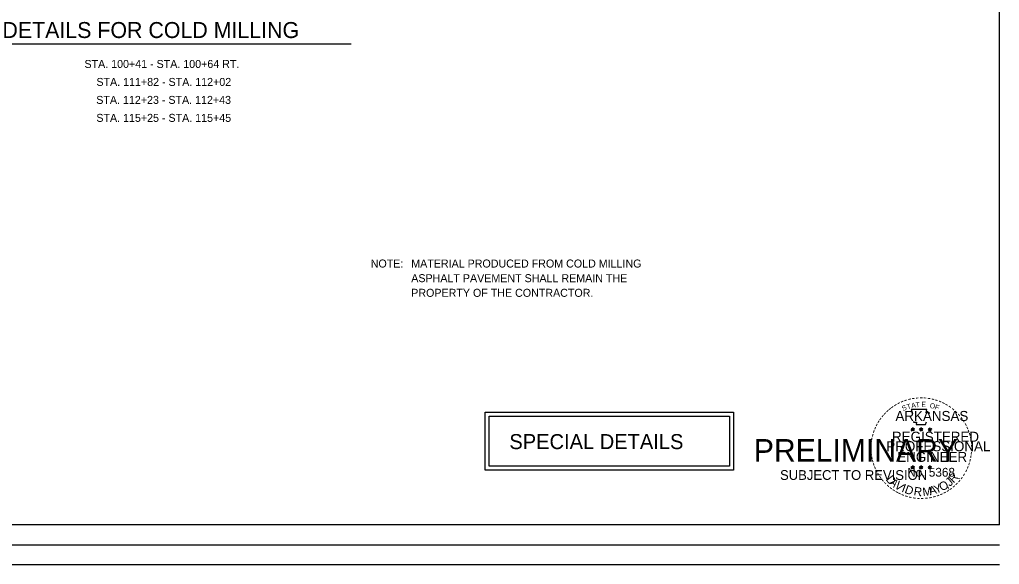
# Model space of a CAD drawing. Extents: x 1944905 to 1956777, y 763871 to 764977.
# Drawn here: x 1952380 to 1953359, y 763871 to 764415 of the extents above; entities that cross this region are included whole.
import ezdxf

# ---------------------------------------------------------------- set-up
doc = ezdxf.new("R2010")
doc.units = 0
for name, color, linetype in [('Default', 7, 'Continuous'), ('R_Border PE', 7, 'Continuous'), ('R_Dimension', 7, 'Continuous')]:
    doc.layers.add(name, color=color, linetype=linetype)

msp = doc.modelspace()

# ---------------------------------------------------------------- linework, layer by layer
at = {"layer": 'Default'}
for p, q in [((1953358.8, 763910.07), (1953358.8, 764937.29)), ((1953358.8, 763910.07), (1951777.89, 763910.07)), ((1951745.05, 763890.36), (1953358.8, 763890.36)), ((1951745.05, 763870.67), (1953358.8, 763870.67))]:
    msp.add_line(p, q, dxfattribs=at)
for points in [[(1952844.89, 764022.9), (1953092.9, 764022.9), (1953092.9, 763964.87), (1952844.89, 763964.87)], [(1952848.89, 764018.9), (1953088.9, 764018.9), (1953088.9, 763968.87), (1952848.89, 763968.87)]]:
    msp.add_lwpolyline(points, close=True, dxfattribs=at)
at = {"layer": 'R_Border PE'}
for p, q in [((1953270.46, 764006.04), (1953272.16, 764005.49)), ((1953270.46, 764006.04), (1953271.71, 764005.89)), ((1953270.46, 764006.04), (1953271.71, 764005.84)), ((1953270.46, 764006.04), (1953271.66, 764005.74)), ((1953270.46, 764006.04), (1953271.66, 764005.54)), ((1953270.46, 764006.04), (1953271.61, 764005.44)), ((1953270.46, 764006.04), (1953271.61, 764005.34)), ((1953272.16, 764007.29), (1953271.91, 764006.09)), ((1953272.16, 764007.29), (1953271.96, 764006.04)), ((1953272.16, 764007.29), (1953272.11, 764006.04)), ((1953272.16, 764005.49), (1953272.16, 764007.29)), ((1953272.16, 764007.29), (1953272.51, 764006.04)), ((1953272.16, 764007.29), (1953272.41, 764006.04)), ((1953272.16, 764007.29), (1953272.31, 764006.09)), ((1953273.91, 764006.04), (1953272.16, 764005.49)), ((1953273.91, 764006.04), (1953272.41, 764005.94)), ((1953273.91, 764006.04), (1953272.51, 764005.79)), ((1953273.91, 764006.04), (1953272.51, 764005.69)), ((1953273.91, 764006.04), (1953272.81, 764005.59)), ((1953273.91, 764006.04), (1953272.91, 764005.54)), ((1953273.91, 764006.04), (1953272.96, 764005.49)), ((1953278.76, 764006.04), (1953280.51, 764005.49)), ((1953278.76, 764006.04), (1953280.06, 764005.89)), ((1953278.76, 764006.04), (1953280.06, 764005.84)), ((1953278.76, 764006.04), (1953280.01, 764005.74)), ((1953278.76, 764006.04), (1953280.01, 764005.54)), ((1953278.76, 764006.04), (1953279.96, 764005.44)), ((1953278.76, 764006.04), (1953279.96, 764005.34)), ((1953280.51, 764007.29), (1953280.26, 764006.09)), ((1953280.51, 764007.29), (1953280.31, 764006.04)), ((1953280.51, 764007.29), (1953280.46, 764006.04)), ((1953280.51, 764005.49), (1953280.51, 764007.29)), ((1953280.51, 764007.29), (1953280.86, 764006.04)), ((1953280.51, 764007.29), (1953280.76, 764006.04)), ((1953280.51, 764007.29), (1953280.66, 764006.09)), ((1953282.26, 764006.04), (1953280.51, 764005.49)), ((1953282.26, 764006.04), (1953280.71, 764005.94)), ((1953282.26, 764006.04), (1953280.81, 764005.79)), ((1953282.26, 764006.04), (1953280.81, 764005.69)), ((1953282.26, 764006.04), (1953281.16, 764005.59)), ((1953282.26, 764006.04), (1953281.26, 764005.54)), ((1953282.26, 764006.04), (1953281.31, 764005.49)), ((1953287.61, 764005.99), (1953289.36, 764005.44)), ((1953287.61, 764005.99), (1953288.91, 764005.84)), ((1953287.61, 764005.99), (1953288.91, 764005.74)), ((1953287.61, 764005.99), (1953288.86, 764005.64)), ((1953287.61, 764005.99), (1953288.81, 764005.49)), ((1953287.61, 764005.99), (1953288.81, 764005.39)), ((1953287.61, 764005.99), (1953288.81, 764005.29)), ((1953289.36, 764007.24), (1953289.06, 764006.04)), ((1953289.36, 764007.24), (1953289.16, 764005.99)), ((1953289.36, 764007.24), (1953289.26, 764005.99)), ((1953289.36, 764005.44), (1953289.36, 764007.24)), ((1953289.36, 764007.24), (1953289.71, 764005.99)), ((1953289.36, 764007.24), (1953289.61, 764005.99)), ((1953289.36, 764007.24), (1953289.46, 764006.04)), ((1953291.11, 764005.99), (1953289.36, 764005.44)), ((1953291.11, 764005.99), (1953289.56, 764005.89)), ((1953291.11, 764005.99), (1953289.66, 764005.74)), ((1953291.11, 764005.99), (1953289.66, 764005.64)), ((1953291.11, 764005.99), (1953290.01, 764005.54)), ((1953291.11, 764005.99), (1953290.06, 764005.49)), ((1953291.11, 764005.99), (1953290.16, 764005.44)), ((1953271.11, 764003.99), (1953272.16, 764005.49)), ((1953271.11, 764003.99), (1953271.66, 764005.39)), ((1953271.11, 764003.99), (1953271.71, 764005.24)), ((1953271.11, 764003.99), (1953271.81, 764005.19)), ((1953271.11, 764003.99), (1953272.16, 764005.09)), ((1953271.11, 764003.99), (1953271.96, 764005.04)), ((1953271.11, 764003.99), (1953272.21, 764004.94)), ((1953273.26, 764003.99), (1953272.16, 764005.49)), ((1953273.26, 764003.99), (1953272.16, 764005.09)), ((1953273.26, 764003.99), (1953272.16, 764004.94)), ((1953273.26, 764003.99), (1953272.36, 764005.04)), ((1953273.26, 764003.99), (1953272.51, 764005.24)), ((1953273.26, 764003.99), (1953272.56, 764005.44)), ((1953273.26, 764003.99), (1953272.66, 764005.44)), ((1953279.46, 764003.99), (1953280.51, 764005.49)), ((1953279.46, 764003.99), (1953280.01, 764005.39)), ((1953279.46, 764003.99), (1953280.06, 764005.24)), ((1953279.46, 764003.99), (1953280.16, 764005.19)), ((1953279.46, 764003.99), (1953280.51, 764005.09)), ((1953279.46, 764003.99), (1953280.31, 764005.04)), ((1953279.46, 764003.99), (1953280.56, 764004.94)), ((1953281.61, 764003.99), (1953280.51, 764005.49)), ((1953281.61, 764003.99), (1953280.51, 764005.09)), ((1953281.61, 764003.99), (1953280.51, 764004.94)), ((1953281.61, 764003.99), (1953280.71, 764005.04)), ((1953281.61, 764003.99), (1953280.86, 764005.24)), ((1953281.61, 764003.99), (1953280.91, 764005.44)), ((1953281.61, 764003.99), (1953281.01, 764005.44)), ((1953288.31, 764003.94), (1953289.36, 764005.44)), ((1953288.31, 764003.94), (1953288.86, 764005.34)), ((1953288.31, 764003.94), (1953288.91, 764005.14)), ((1953288.31, 764003.94), (1953289.01, 764005.14)), ((1953288.31, 764003.94), (1953289.36, 764005.04)), ((1953288.31, 764003.94), (1953289.16, 764004.99)), ((1953288.31, 764003.94), (1953289.41, 764004.89)), ((1953290.41, 764003.94), (1953289.36, 764005.44)), ((1953290.41, 764003.94), (1953289.36, 764005.04)), ((1953290.41, 764003.94), (1953289.36, 764004.89)), ((1953290.41, 764003.94), (1953289.56, 764004.99)), ((1953290.41, 764003.94), (1953289.71, 764005.19)), ((1953290.41, 764003.94), (1953289.76, 764005.39)), ((1953290.41, 764003.94), (1953289.86, 764005.39)), ((1953270.41, 763968.19), (1953272.16, 763967.64)), ((1953270.41, 763968.19), (1953271.71, 763968.04)), ((1953270.41, 763968.19), (1953271.71, 763967.94)), ((1953270.41, 763968.19), (1953271.66, 763967.84)), ((1953270.41, 763968.19), (1953271.61, 763967.69)), ((1953270.41, 763968.19), (1953271.61, 763967.59)), ((1953270.41, 763968.19), (1953271.61, 763967.44)), ((1953271.11, 763966.14), (1953272.16, 763967.64)), ((1953271.11, 763966.14), (1953271.66, 763967.54)), ((1953271.11, 763966.14), (1953271.71, 763967.34)), ((1953271.11, 763966.14), (1953271.81, 763967.29)), ((1953271.11, 763966.14), (1953272.16, 763967.24)), ((1953271.11, 763966.14), (1953271.96, 763967.19)), ((1953271.11, 763966.14), (1953272.21, 763967.09)), ((1953272.16, 763969.44), (1953271.86, 763968.24)), ((1953272.16, 763969.44), (1953271.96, 763968.19)), ((1953272.16, 763969.44), (1953272.06, 763968.19)), ((1953272.16, 763967.64), (1953272.16, 763969.44)), ((1953272.16, 763969.44), (1953272.51, 763968.19)), ((1953272.16, 763969.44), (1953272.41, 763968.19)), ((1953272.16, 763969.44), (1953272.26, 763968.19)), ((1953273.91, 763968.19), (1953272.16, 763967.64)), ((1953273.21, 763966.14), (1953272.16, 763967.64)), ((1953273.21, 763966.14), (1953272.16, 763967.19)), ((1953273.21, 763966.14), (1953272.16, 763967.09)), ((1953273.91, 763968.19), (1953272.36, 763968.09)), ((1953273.21, 763966.14), (1953272.36, 763967.19)), ((1953273.91, 763968.19), (1953272.46, 763967.94)), ((1953273.91, 763968.19), (1953272.46, 763967.84)), ((1953273.21, 763966.14), (1953272.51, 763967.34)), ((1953273.21, 763966.14), (1953272.56, 763967.59)), ((1953273.21, 763966.14), (1953272.66, 763967.59)), ((1953273.91, 763968.19), (1953272.81, 763967.74)), ((1953273.91, 763968.19), (1953272.86, 763967.69)), ((1953273.91, 763968.19), (1953272.96, 763967.59)), ((1953278.76, 763968.19), (1953280.51, 763967.64)), ((1953278.76, 763968.19), (1953280.06, 763968.04)), ((1953278.76, 763968.19), (1953280.01, 763967.94)), ((1953278.76, 763968.19), (1953280.01, 763967.84)), ((1953278.76, 763968.19), (1953279.96, 763967.69)), ((1953278.76, 763968.19), (1953279.96, 763967.59)), ((1953278.76, 763968.19), (1953279.96, 763967.44)), ((1953279.41, 763966.14), (1953280.51, 763967.64)), ((1953279.41, 763966.14), (1953280.01, 763967.54)), ((1953279.41, 763966.14), (1953280.06, 763967.34)), ((1953279.41, 763966.14), (1953280.16, 763967.29)), ((1953279.41, 763966.14), (1953280.51, 763967.24)), ((1953279.41, 763966.14), (1953280.31, 763967.19)), ((1953279.41, 763966.14), (1953280.51, 763967.09)), ((1953280.51, 763969.44), (1953280.21, 763968.24)), ((1953280.51, 763969.44), (1953280.31, 763968.19)), ((1953280.51, 763969.44), (1953280.41, 763968.19)), ((1953280.51, 763967.64), (1953280.51, 763969.44)), ((1953280.51, 763969.44), (1953280.86, 763968.19)), ((1953280.51, 763969.44), (1953280.76, 763968.19)), ((1953280.51, 763969.44), (1953280.61, 763968.19)), ((1953282.26, 763968.19), (1953280.51, 763967.64)), ((1953281.56, 763966.14), (1953280.51, 763967.64)), ((1953281.56, 763966.14), (1953280.51, 763967.19)), ((1953281.56, 763966.14), (1953280.51, 763967.09)), ((1953282.26, 763968.19), (1953280.71, 763968.09)), ((1953281.56, 763966.14), (1953280.71, 763967.19)), ((1953282.26, 763968.19), (1953280.81, 763967.94)), ((1953282.26, 763968.19), (1953280.81, 763967.84)), ((1953281.56, 763966.14), (1953280.86, 763967.34)), ((1953281.56, 763966.14), (1953280.91, 763967.59)), ((1953281.56, 763966.14), (1953281.01, 763967.59)), ((1953282.26, 763968.19), (1953281.11, 763967.74)), ((1953282.26, 763968.19), (1953281.21, 763967.69)), ((1953282.26, 763968.19), (1953281.31, 763967.59)), ((1953287.61, 763968.14), (1953289.36, 763967.54)), ((1953287.61, 763968.14), (1953288.86, 763967.99)), ((1953287.61, 763968.14), (1953288.86, 763967.89)), ((1953287.61, 763968.14), (1953288.81, 763967.79)), ((1953287.61, 763968.14), (1953288.81, 763967.64)), ((1953287.61, 763968.14), (1953288.76, 763967.49)), ((1953287.61, 763968.14), (1953288.76, 763967.39)), ((1953288.26, 763966.09), (1953289.36, 763967.54)), ((1953288.26, 763966.09), (1953288.81, 763967.44)), ((1953288.26, 763966.09), (1953288.91, 763967.29)), ((1953288.26, 763966.09), (1953289.01, 763967.24)), ((1953288.26, 763966.09), (1953289.16, 763967.14)), ((1953288.26, 763966.09), (1953289.31, 763967.14)), ((1953288.26, 763966.09), (1953289.36, 763967.04)), ((1953289.36, 763969.39), (1953289.06, 763968.14)), ((1953289.36, 763969.39), (1953289.16, 763968.14)), ((1953289.36, 763969.39), (1953289.26, 763968.14)), ((1953290.41, 763966.09), (1953289.31, 763967.14)), ((1953290.41, 763966.09), (1953289.31, 763966.99)), ((1953289.36, 763967.54), (1953289.36, 763969.39)), ((1953289.36, 763969.39), (1953289.66, 763968.14)), ((1953289.36, 763969.39), (1953289.61, 763968.14)), ((1953289.36, 763969.39), (1953289.46, 763968.14)), ((1953291.06, 763968.14), (1953289.36, 763967.54)), ((1953290.41, 763966.09), (1953289.36, 763967.54)), ((1953290.41, 763966.09), (1953289.51, 763967.14)), ((1953291.06, 763968.14), (1953289.56, 763967.99)), ((1953291.06, 763968.14), (1953289.66, 763967.89)), ((1953291.06, 763968.14), (1953289.66, 763967.79)), ((1953290.41, 763966.09), (1953289.71, 763967.54)), ((1953290.41, 763966.09), (1953289.71, 763967.29)), ((1953290.41, 763966.09), (1953289.86, 763967.54)), ((1953291.06, 763968.14), (1953289.96, 763967.64)), ((1953291.06, 763968.14), (1953290.06, 763967.59)), ((1953291.06, 763968.14), (1953290.11, 763967.54))]:
    msp.add_line(p, q, dxfattribs=at)
for points in [[(1953270.66, 764025.44), (1953272.01, 764021.29)], [(1953288.21, 764020.84), (1953288.91, 764022.24), (1953285.46, 764022.14), (1953286.21, 764025.44), (1953270.66, 764025.44)], [(1953272.16, 764007.29), (1953273.26, 764003.99), (1953270.46, 764006.04), (1953273.91, 764006.04), (1953271.11, 764003.99), (1953272.16, 764007.29)], [(1953273.11, 764013.34), (1953273.11, 764012.89), (1953275.91, 764012.79), (1953275.66, 764010.44), (1953285.01, 764010.44), (1953286.01, 764013.09)], [(1953280.51, 764007.29), (1953281.61, 764003.99), (1953278.76, 764006.04), (1953282.26, 764006.04), (1953279.46, 764003.99), (1953280.51, 764007.29)], [(1953289.36, 764007.24), (1953290.41, 764003.94), (1953287.61, 764005.99), (1953291.11, 764005.99), (1953288.31, 764003.94), (1953289.36, 764007.24)], [(1953272.16, 763969.44), (1953273.21, 763966.14), (1953270.41, 763968.19), (1953273.91, 763968.19), (1953271.11, 763966.14), (1953272.16, 763969.44)], [(1953280.51, 763969.44), (1953281.56, 763966.14), (1953278.76, 763968.19), (1953282.26, 763968.19), (1953279.41, 763966.14), (1953280.51, 763969.44)], [(1953289.36, 763969.39), (1953290.41, 763966.09), (1953287.61, 763968.14), (1953291.06, 763968.14), (1953288.26, 763966.09), (1953289.36, 763969.39)]]:
    msp.add_lwpolyline(points, dxfattribs=at)
for centre, radius in [((1953272.16, 764005.49), 0.861), ((1953272.16, 764005.49), 0.78), ((1953272.16, 764005.49), 0.723), ((1953272.16, 764005.49), 0.664), ((1953272.16, 764005.49), 0.579), ((1953272.16, 764005.49), 0.537), ((1953272.16, 764005.49), 0.495), ((1953272.16, 764005.49), 0.426), ((1953272.16, 764005.49), 0.374), ((1953280.5, 764005.49), 0.861), ((1953280.5, 764005.49), 0.78), ((1953280.5, 764005.49), 0.723), ((1953280.5, 764005.49), 0.664), ((1953280.5, 764005.49), 0.579), ((1953280.5, 764005.49), 0.537), ((1953280.5, 764005.49), 0.495), ((1953280.5, 764005.49), 0.426), ((1953280.5, 764005.49), 0.374), ((1953289.34, 764005.43), 0.861), ((1953289.34, 764005.43), 0.78), ((1953289.34, 764005.43), 0.723), ((1953289.34, 764005.43), 0.664), ((1953289.34, 764005.43), 0.579), ((1953289.34, 764005.43), 0.537), ((1953289.34, 764005.43), 0.495), ((1953289.34, 764005.43), 0.426), ((1953272.16, 764005.49), 0.311), ((1953272.16, 764005.49), 0.248), ((1953272.16, 764005.49), 0.185), ((1953272.16, 764005.49), 0.148), ((1953272.16, 764005.49), 0.0721), ((1953280.5, 764005.49), 0.311), ((1953280.5, 764005.49), 0.248), ((1953280.5, 764005.49), 0.185), ((1953280.5, 764005.49), 0.148), ((1953280.5, 764005.49), 0.0721), ((1953289.34, 764005.43), 0.374), ((1953289.34, 764005.43), 0.311), ((1953289.34, 764005.43), 0.248), ((1953289.34, 764005.43), 0.185), ((1953289.34, 764005.43), 0.148), ((1953289.34, 764005.43), 0.0721), ((1953272.14, 763967.63), 0.861), ((1953272.14, 763967.63), 0.78), ((1953272.14, 763967.63), 0.723), ((1953272.14, 763967.63), 0.664), ((1953272.14, 763967.63), 0.579), ((1953272.14, 763967.63), 0.537), ((1953272.14, 763967.63), 0.495), ((1953272.14, 763967.63), 0.426), ((1953272.14, 763967.63), 0.374), ((1953272.14, 763967.63), 0.311), ((1953272.14, 763967.63), 0.248), ((1953272.14, 763967.63), 0.185), ((1953272.14, 763967.63), 0.148), ((1953272.14, 763967.63), 0.0721), ((1953280.48, 763967.63), 0.861), ((1953280.48, 763967.63), 0.78), ((1953280.48, 763967.63), 0.723), ((1953280.48, 763967.63), 0.664), ((1953280.48, 763967.63), 0.579), ((1953280.48, 763967.63), 0.537), ((1953280.48, 763967.63), 0.495), ((1953280.48, 763967.63), 0.426), ((1953280.48, 763967.63), 0.374), ((1953280.48, 763967.63), 0.311), ((1953280.48, 763967.63), 0.248), ((1953280.48, 763967.63), 0.185), ((1953280.48, 763967.63), 0.148), ((1953280.48, 763967.63), 0.0721), ((1953289.32, 763967.57), 0.861), ((1953289.32, 763967.57), 0.78), ((1953289.32, 763967.57), 0.723), ((1953289.32, 763967.57), 0.664), ((1953289.32, 763967.57), 0.579), ((1953289.32, 763967.57), 0.537), ((1953289.32, 763967.57), 0.495), ((1953289.32, 763967.57), 0.426), ((1953289.32, 763967.57), 0.374), ((1953289.32, 763967.57), 0.311), ((1953289.32, 763967.57), 0.248), ((1953289.32, 763967.57), 0.185), ((1953289.32, 763967.57), 0.148), ((1953289.32, 763967.57), 0.0721)]:
    msp.add_circle(centre, radius, dxfattribs=at)
at = {"layer": 'R_Dimension'}
msp.add_line((1952363.95, 764390.69), (1952710.98, 764390.69), dxfattribs=at)

# ---------------------------------------------------------------- texts
at = {"layer": 'Default'}
for s, height, p in [('SPECIAL DETAILS', 15, (1952869.08, 763985.86)), ('PRELIMINARY', 22.5, (1953113.39, 763973.37)), ('        SUBJECT TO REVISION', 9.75, (1953110.57, 763955.1))]:
    msp.add_text(s, height=height, dxfattribs=at).set_placement(p)
at = {"layer": 'R_Border PE'}
for s, height, rotation, p in [('-', 8, 19.17608, (1953264.36, 764031.09)), ('-', 8, 13.63015, (1953268.11, 764032.29)), ('-', 8, 10.21935, (1953271.51, 764033.09)), ('-', 8, 5.89682, (1953275.16, 764033.64)), ('-', 8, 0.18623, (1953279.01, 764033.99)), ('-', 8, 357.74304, (1953282.66, 764033.94)), ('-', 8, 352.16173, (1953286.36, 764033.64)), ('-', 8, 347.20489, (1953289.96, 764033.09)), ('-', 8, 342.3362, (1953293.11, 764032.29)), ('-', 8, 38.95066, (1953249.81, 764022.44)), ('-', 8, 36.23174, (1953252.16, 764024.29)), ('-', 8, 34.06357, (1953255.06, 764026.29)), ('-', 8, 28.79182, (1953258.06, 764028.14)), ('-', 8, 24.30721, (1953261.21, 764029.74)), ('S', 5, 21.59401, (1953262.41, 764023.84)), ('T', 5, 16.4036, (1953267.01, 764025.49)), ('A', 5, 11.21318, (1953271.11, 764026.74)), ('T', 5, 6.02276, (1953275.36, 764027.54)), ('E', 5, 0.83234, (1953280.91, 764028.09)), ('O', 5, 350.4515, (1953288.91, 764027.04)), ('F', 5, 340.07066, (1953293.66, 764025.94)), ('-', 8, 337.85509, (1953296.81, 764031.19)), ('-', 8, 334.12109, (1953299.96, 764029.84)), ('-', 8, 329.64089, (1953302.86, 764028.44)), ('-', 8, 325.86266, (1953306.06, 764026.59)), ('-', 8, 320.52971, (1953309.11, 764024.49)), ('-', 8, 54.23247, (1953241.31, 764012.69)), ('-', 8, 50.61417, (1953243.36, 764015.54)), ('-', 8, 48.42305, (1953245.41, 764017.94)), ('-', 8, 42.96224, (1953247.61, 764020.34)), ('-', 8, 315.57859, (1953312.11, 764022.04)), ('-', 8, 309.87973, (1953314.96, 764019.29)), ('-', 8, 306.65218, (1953317.61, 764016.29)), ('-', 8, 67.77427, (1953236.81, 764003.94)), ('-', 8, 62.87135, (1953238.11, 764006.99)), ('-', 8, 58.07063, (1953239.66, 764010.04)), ('-', 7, 303.67529, (1953320.01, 764013.44)), ('-', 8, 299.66835, (1953321.61, 764010.39)), ('-', 8, 294.66279, (1953323.21, 764007.34)), ('-', 8, 81.20126, (1953234.06, 763993.64)), ('-', 8, 75.46096, (1953234.76, 763997.19)), ('-', 8, 72.39447, (1953235.71, 764000.79)), ('-', 8, 290.57283, (1953324.51, 764004.44)), ('-', 8, 285.12326, (1953325.71, 764001.54)), ('-', 8, 280.54934, (1953326.71, 763997.84)), ('-', 8, 89.06224, (1953233.56, 763986.69)), ('-', 8, 85.18634, (1953233.71, 763990.19)), ('-', 8, 276.59616, (1953327.51, 763993.99)), ('-', 8, 274.33011, (1953327.81, 763990.39)), ('-', 8, 269.94067, (1953327.96, 763987.24)), ('-', 8, 94.19588, (1953233.76, 763983.04)), ('-', 8, 98.94793, (1953234.11, 763979.74)), ('-', 8, 101.71495, (1953234.81, 763976.04)), ('-', 8, 260.99529, (1953327.51, 763980.64)), ('-', 8, 263.5172, (1953327.86, 763983.89)), ('-', 8, 105.45785, (1953235.61, 763973.09)), ('-', 8, 109.08742, (1953236.66, 763969.94)), ('-', 8, 114.06432, (1953237.96, 763966.94)), ('-', 8, 247.88866, (1953324.96, 763970.29)), ('-', 8, 252.86809, (1953326.06, 763973.64)), ('-', 8, 255.7626, (1953326.96, 763977.24)), ('-', 8, 115.72885, (1953239.46, 763963.84)), ('-', 8, 120.44712, (1953241.26, 763960.94)), ('-', 8, 125.89344, (1953243.26, 763958.14)), ('D', 8.47, 308.02669, (1953244.81, 763955.44)), ('J', 8.47, 40.15065, (1953309.16, 763948.09)), ('R', 8.47, 46.29225, (1953312.91, 763951.44)), ('-', 8, 233.84524, (1953319.66, 763960.14)), ('-', 8, 239.07125, (1953321.66, 763963.39)), ('-', 8, 244.61971, (1953323.66, 763967.14)), ('-', 8, 130.71812, (1953245.56, 763955.34)), ('-', 8, 134.22381, (1953248.16, 763952.64)), ('-', 8, 138.93382, (1953250.81, 763950.29)), ('A', 7.7, 314.16829, (1953248.56, 763951.99)), ('-', 8, 144.64634, (1953253.56, 763948.29)), ('V', 8.47, 322.07513, (1953253.21, 763947.94)), ('ID', 8.47, 339.24466, (1953260.46, 763943.49)), ('R', 8.47, 351.48461, (1953272.76, 763939.94)), ('M', 8.47, 7.38422, (1953282.46, 763938.79)), ('A', 8.47, 15.04444, (1953289.46, 763939.74)), ('Y', 8.47, 21.72586, (1953295.26, 763941.09)), ('O', 8.47, 27.86746, (1953301.16, 763943.49)), (',', 8.45, 13.66842, (1953306.01, 763946.74)), ('-', 8, 215.73633, (1953309.76, 763949.54)), ('-', 8, 221.08509, (1953312.51, 763951.94)), ('-', 8, 225.76533, (1953315.11, 763954.49)), ('-', 8, 231.25377, (1953317.51, 763957.29)), ('-', 8, 148.08978, (1953256.36, 763946.44)), ('-', 8, 151.57039, (1953259.26, 763944.79)), ('-', 8, 154.60019, (1953261.86, 763943.59)), ('-', 8, 158.56121, (1953265.01, 763942.29)), ('-', 8, 162.79826, (1953268.41, 763941.24)), ('-', 8, 167.55551, (1953272.01, 763940.39)), ('-', 8, 173.11546, (1953275.86, 763939.84)), ('.', 7.7, 351.01787, (1953278.56, 763938.99)), ('-', 8, 185.81666, (1953287.36, 763940.09)), ('-', 8, 191.28576, (1953291.06, 763940.74)), ('-', 8, 195.47429, (1953294.71, 763941.74)), ('-', 8, 200.71842, (1953298.06, 763942.94)), ('-', 8, 204.25161, (1953301.16, 763944.29)), ('-', 8, 207.35684, (1953304.31, 763945.89)), ('-', 8, 212.24909, (1953307.11, 763947.64)), ('-', 8, 176.51827, (1953279.61, 763939.59)), ('-', 8, 181.59176, (1953283.31, 763939.69))]:
    msp.add_text(s, height=height, rotation=rotation, dxfattribs=at).set_placement(p)
for s, height, p in [('ARKANSAS', 10, (1953254.91, 764013.99)), ('REGISTERED', 10, (1953251.51, 763993.24)), ('PROFESSIONAL', 9.9999, (1953245.76, 763983.74)), ('ENGINEER', 10, (1953256.71, 763973.09)), ('No. 5368', 8.785, (1953266.71, 763958.34)), ('.', 8.45, (1953316.96, 763955.84))]:
    msp.add_text(s, height=height, dxfattribs=at).set_placement(p)
at = {"layer": 'R_Dimension'}
for s, height, p in [('DETAILS FOR COLD MILLING', 15.963, (1952362.44, 764396.6)), ('STA. 100+41 - STA. 100+64 RT.', 7.9815, (1952444.42, 764366.7)), ('STA. 111+82 - STA. 112+02', 7.9815, (1952456.38, 764348.74)), ('STA. 112+23 - STA. 112+43', 7.9815, (1952456.23, 764330.78)), ('STA. 115+25 - STA. 115+45', 7.9815, (1952456.31, 764312.83)), ('NOTE: ', 7.982, (1952730.53, 764167.29)), ('MATERIAL PRODUCED FROM COLD MILLING', 7.9815, (1952771.01, 764167.29)), ('ASPHALT PAVEMENT SHALL REMAIN THE', 7.9815, (1952771.01, 764152.66)), ('PROPERTY OF THE CONTRACTOR.', 7.9815, (1952771.01, 764138.03))]:
    msp.add_text(s, height=height, dxfattribs=at).set_placement(p)

doc.saveas('drawing.dxf')
